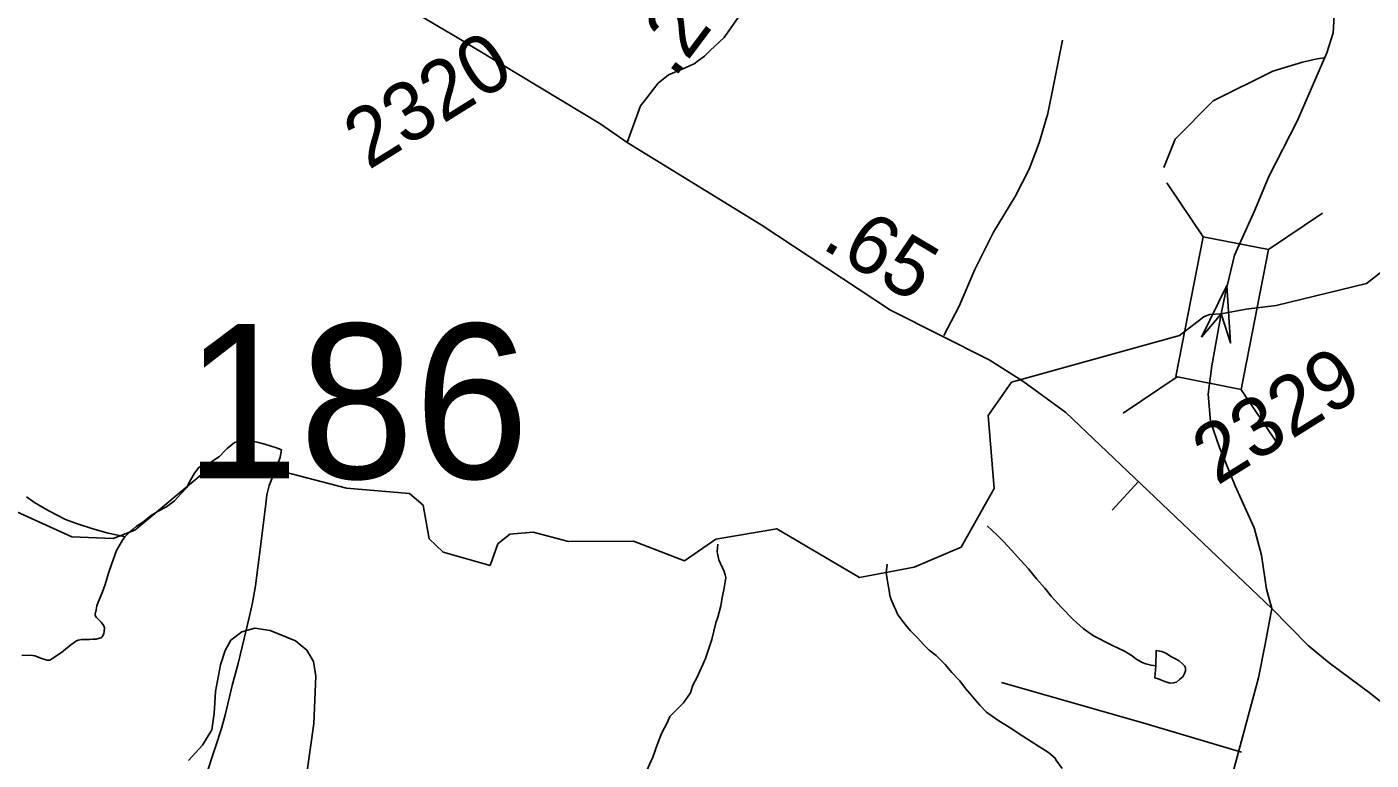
# Model space of a CAD drawing. Extents: x 2001466 to 31450019, y -30647475 to 847247.
# Drawn here: x 2180389 to 2186094, y 761240 to 764352 of the extents above; entities that cross this region are included whole.
import ezdxf

# ---------------------------------------------------------------- set-up
doc = ezdxf.new("R2010")
doc.units = 0
for name, color, linetype in [('Exist Hydrographic Creek Single Shore', 7, 'Continuous'), ('Exist Hydrographic Misc Water Feature', 7, 'Continuous'), ('Exist Road Non-System Type 51', 7, 'Continuous'), ('Exist Road Secondary Mileage Hundredths English Label', 7, 'Continuous'), ('Exist Road Secondary Structure Standard Bridge Attributed CELL', 7, 'Continuous'), ('Exist Road Secondary Structure Standard Bridge CELL', 7, 'Continuous'), ('Exist Road Secondary Structure Standard Bridge Number Label', 7, 'Continuous'), ('Exist Road Secondary Type 51 Attributed', 7, 'Continuous'), ('Exist Road Secondary Type 51 Number Label', 7, 'Continuous')]:
    doc.layers.add(name, color=color, linetype=linetype)

msp = doc.modelspace()

# ---------------------------------------------------------------- linework, layer by layer
at = {"layer": 'Exist Hydrographic Creek Single Shore'}
for points in [[(2185280, 763041.8), (2185383.3, 763121), (2185407.5, 763131.3), (2185458.1, 763134.6), (2185563.6, 763153.3), (2185690.4, 763169.4), (2186074, 763262.7), (2186439, 763547.1), (2186887, 763744.6), (2187202, 764030.1), (2187409.1, 764147.2)], [(2185280, 763041.8), (2184567.1, 762844.2), (2184468, 762701.9), (2184494.1, 762393), (2184354, 762143.3), (2184155.1, 762058.8), (2183922, 762014.4), (2183571.1, 762221.7), (2183313, 762177.8), (2183180.1, 762085.4), (2182962.9, 762168.6), (2182688, 762167.6), (2182538.1, 762206.8), (2182438, 762199), (2182388, 762157.4), (2182355, 762066.2), (2182155, 762122.8), (2182096, 762179.8), (2182070.2, 762321.4), (2182012.1, 762371.8), (2181745.1, 762393.7), (2181311, 762507.5), (2181145.2, 762465), (2180847, 762215.3), (2180755.2, 762181.1), (2180580, 762188), (2180346.1, 762294.4)]]:
    msp.add_lwpolyline(points, dxfattribs=at)
at = {"layer": 'Exist Hydrographic Misc Water Feature'}
for points in [[(2180804.6, 762188), (2180810.1, 762194), (2180822.4, 762206.3), (2180840.5, 762220.3), (2180854, 762232.4), (2180865.9, 762240.4), (2180886, 762254.3), (2180916.1, 762278.6), (2180945.9, 762296.8), (2180981.5, 762315), (2181015.6, 762341), (2181043.3, 762371.3), (2181067, 762397.3), (2181080.8, 762423.7), (2181089.2, 762437.4), (2181100.9, 762457.6), (2181118.5, 762481.7), (2181134.3, 762489.8), (2181158.3, 762495.9), (2181178.6, 762510.3), (2181206.3, 762528.1), (2181228.4, 762552.3), (2181238.3, 762562.6), (2181270.2, 762588.5), (2181306.1, 762596.9), (2181326, 762594.7), (2181344.1, 762593.2), (2181366, 762589.1), (2181398.2, 762581.4), (2181452.1, 762563.5), (2181470, 762557.5)], [(2181154, 761188.3), (2181177.4, 761262.7), (2181191.3, 761300.7), (2181212.8, 761370.5), (2181230.5, 761430.7), (2181260, 761556.9), (2181285.4, 761650.8), (2181310.6, 761756.9), (2181332.2, 761845.3), (2181345.9, 761907.4), (2181359.2, 761979.2), (2181370.7, 762069.5), (2181380.6, 762145.5), (2181390, 762225.2), (2181401.5, 762315.6), (2181407.2, 762365.4), (2181416.9, 762405.3), (2181436.7, 762455.5), (2181454.4, 762497.8), (2181464.2, 762525.5), (2181470, 762557.5)], [(2180387.3, 762357.7), (2180421.7, 762333.9), (2180465.8, 762306.1), (2180514, 762280.6), (2180552.2, 762260.6), (2180600.1, 762244.8), (2180668.6, 762221.5), (2180734.4, 762203.8), (2180794.1, 762189.9)], [(2185179.8, 761640.7), (2185160.1, 761642.8), (2185137.7, 761648.6), (2185121.7, 761654.7), (2185095.9, 761670.4), (2185079.5, 761682.2), (2185047.7, 761702.1), (2184993.6, 761727.6), (2184915.2, 761767.5), (2184871.4, 761799.2), (2184829.1, 761836.9), (2184778.7, 761888.7), (2184736.4, 761936.5), (2184708.6, 761969.9), (2184673.9, 762010), (2184639.7, 762051.7), (2184607.3, 762087.4), (2184567.5, 762131.2), (2184533, 762167.2), (2184507.2, 762195), (2184465, 762234.7)], [(2180367.4, 761683.7), (2180405.1, 761686.1), (2180423.2, 761682.1), (2180447.6, 761672.4), (2180473.8, 761664.3), (2180485.7, 761664.6), (2180501.3, 761674.4), (2180507.2, 761678.8), (2180535.3, 761696.8), (2180553.4, 761710.7), (2180575.1, 761729), (2180589.1, 761739), (2180596.9, 761745.1), (2180606.9, 761749.3), (2180620.8, 761751.3), (2180631.1, 761751.3), (2180654.9, 761751.4), (2180668.8, 761753.3), (2180682.8, 761753.6), (2180696.7, 761757.6), (2180704.7, 761759.7), (2180710.7, 761767.7), (2180715, 761777.6), (2180716.6, 761785.8), (2180718.4, 761801.8), (2180714.8, 761809.7), (2180708.6, 761819.5), (2180704.7, 761825.8), (2180690.4, 761839.7), (2180684.6, 761845.5), (2180680.5, 761851.4), (2180678.1, 761855.4), (2180678.5, 761859.4), (2180682.2, 761877.5), (2180686.1, 761895.5), (2180691.8, 761909.7), (2180699.8, 761929.6), (2180709.8, 761953.6), (2180721.5, 761985.5), (2180735.5, 762033.7), (2180749, 762073.9), (2180768.9, 762130), (2180794.5, 762174.1), (2180804.6, 762188)], [(2180794.1, 762189.9), (2180804.6, 762188)], [(2183011.3, 761177), (2183044.8, 761253), (2183064.4, 761305.2), (2183082.3, 761353.3), (2183108.1, 761401.3), (2183117.8, 761425.4), (2183145.7, 761453.6), (2183175.4, 761483.6), (2183205.3, 761525.7), (2183215, 761558), (2183233, 761592.1), (2183268.5, 761672), (2183295.7, 761752.2), (2183313.4, 761822.2), (2183321.6, 761846.5), (2183333.5, 761894.5), (2183339, 761930.2), (2183346.8, 761962.3), (2183352.5, 761996.4), (2183354.8, 762014.7), (2183352.5, 762026.4), (2183348.4, 762040.4), (2183340.4, 762056.2), (2183332.5, 762074.4), (2183326.1, 762090.4), (2183322.2, 762104.4), (2183320.4, 762116.4), (2183318.1, 762126.1), (2183321.8, 762156.3)], [(2184782.6, 761205), (2184756.1, 761240.6), (2184752.4, 761248.5), (2184724.6, 761272.6), (2184686, 761296.3), (2184615.9, 761341.8), (2184561.3, 761377.6), (2184509.2, 761409.3), (2184461.5, 761443), (2184432.8, 761472.9), (2184412.9, 761496.5), (2184392.8, 761520.7), (2184372.9, 761544.4), (2184348.5, 761576.1), (2184314.4, 761612), (2184286.6, 761645.9), (2184248.2, 761683.7), (2184218.1, 761707.3), (2184194.1, 761731.2), (2184169.5, 761757.3), (2184139.5, 761789), (2184123.3, 761806.8), (2184107.5, 761826.7), (2184085, 761856.9), (2184074.9, 761880.7), (2184069.2, 761892.5), (2184056.7, 761922.4), (2184051, 761938.3), (2184048.7, 761960.5), (2184044.6, 761982.2), (2184040.5, 762008.4), (2184036.2, 762036.2), (2184040.1, 762072.2)], [(2185179.8, 761640.7), (2185181.6, 761704.9), (2185205.6, 761700.9), (2185219.3, 761695.1), (2185233.9, 761687.3), (2185243.5, 761679.3), (2185264, 761669.3), (2185279.6, 761661.3), (2185293.8, 761649.4), (2185302, 761639.7), (2185306.3, 761631.7), (2185305.9, 761619.6), (2185302.2, 761607.6), (2185294.2, 761593.4), (2185282.5, 761583.4), (2185268.6, 761571.3), (2185254.2, 761567.4), (2185240.3, 761567.1), (2185218.3, 761573.2), (2185204.4, 761579), (2185190, 761585.2), (2185176.3, 761588.9), (2185179.8, 761640.7)]]:
    msp.add_lwpolyline(points, dxfattribs=at)
at = {"layer": 'Exist Road Non-System Type 51'}
for points in [[(2184280.6, 763042.7), (2184346, 763167), (2184411.9, 763322), (2184491, 763480.3), (2184583.3, 763632), (2184642.6, 763747.4), (2184685.5, 763859.5), (2184721.7, 763984.8), (2184748.1, 764116.7), (2184784.3, 764294.8)], [(2185896.4, 764220.4), (2185864.5, 764215.7), (2185802.3, 764202.1), (2185676.6, 764164.2), (2185423.7, 764038.4), (2185262.8, 763874.7), (2185214.1, 763755.6)], [(2184994.2, 762301.4), (2185106.8, 762422.2)], [(2181563.7, 761094), (2181607.1, 761395.9), (2181614.9, 761597), (2181605.1, 761658.1), (2181577.5, 761707.3), (2181528.3, 761746.8), (2181421.9, 761790.1), (2181356.9, 761800), (2181301.8, 761784.2), (2181254.5, 761748.7), (2181230.9, 761705.4), (2181211.2, 761644.3), (2181189.5, 761531.9), (2181183.6, 761437.3), (2181173.4, 761368.3), (2181134, 761303.3), (2181074.9, 761238.3)], [(2184525.6, 761569.4), (2185125.4, 761398), (2185543.5, 761274)]]:
    msp.add_lwpolyline(points, dxfattribs=at)
at = {"layer": 'Exist Road Secondary Structure Standard Bridge Attributed CELL'}
msp.add_lwpolyline([(2185373.8, 763035.7), (2185482.2, 763254.1), (2185497.5, 763010.8), (2185458.1, 763134.6)], close=True, dxfattribs=at)
at = {"layer": 'Exist Road Secondary Structure Standard Bridge CELL'}
for p, q in [((2185227.5, 763690.1), (2185381.5, 763461.1)), ((2185887.6, 763560.7), (2185658.5, 763406.8)), ((2185270.1, 762867), (2185041.1, 762713)), ((2185540.9, 762813.9), (2185694.9, 762584.8))]:
    msp.add_line(p, q, dxfattribs=at)
msp.add_lwpolyline([(2185658.5, 763406.8), (2185542.2, 762813.6), (2185265.2, 762867.9), (2185381.5, 763461.1)], close=True, dxfattribs=at)
at = {"layer": 'Exist Road Secondary Type 51 Attributed'}
for points in [[(2179690.4, 765365.9), (2180040.8, 765295.9), (2180213.4, 765261.3), (2180622.1, 765153.5), (2180858.5, 765074.9), (2181089.3, 764970.2), (2181318.4, 764839.3), (2181497.4, 764729.4), (2182207.3, 764311.6), (2182824.2, 763938.8), (2182937.2, 763861.3)], [(2185458.1, 763134.6), (2185475.7, 763223.4), (2185514.6, 763383.6), (2185599.8, 763574.1), (2185659.5, 763716.5), (2185780.3, 763952.1), (2185905.4, 764241.2), (2185932.6, 764326), (2185937.8, 764424.4), (2185928.4, 764507.1), (2185862, 764650.6), (2185787.9, 764814.2), (2185702.9, 764971.2)], [(2182937.2, 763861.3), (2182992.5, 764016.1), (2183015.3, 764044.9), (2183033.5, 764069.2), (2183048.7, 764087.4), (2183068.4, 764113.3), (2183112.4, 764148.2), (2183173.2, 764174), (2183220.2, 764195.3), (2183239.9, 764208.9), (2183264.2, 764227.2), (2183288.9, 764251.5), (2183347.7, 764306.1), (2183397.8, 764377.5), (2183414.5, 764401.8), (2183429.7, 764421.5), (2183454, 764454.9), (2183522.3, 764585.5), (2183551.1, 764649.3)], [(2182937.2, 763861.3), (2183504.9, 763511.6), (2184054.7, 763149.3), (2184473.3, 762938.8), (2184615.1, 762847.7), (2184798.2, 762715.8), (2185672.5, 761883.2)], [(2185672.5, 761883.2), (2185650.1, 761965.7), (2185628.1, 762110.3), (2185597.7, 762225.4), (2185516.7, 762404.5), (2185450.7, 762566.8), (2185411.9, 762676.5), (2185401.7, 762793.6), (2185417.8, 762913.9), (2185458.1, 763134.6)], [(2185346.1, 759130.3), (2185337.7, 759348.1), (2185327.2, 759589), (2185309.4, 759796.3), (2185322, 760095.8), (2185365.9, 760382.7), (2185417.7, 760688.4), (2185500.9, 761164.9), (2185548, 761337.7), (2185615.5, 761589), (2185643.8, 761732.4), (2185672.5, 761883.2)], [(2185672.5, 761883.2), (2185826.3, 761726.2), (2185915.2, 761652.9), (2186091, 761523.1), (2186502.7, 761193.2), (2186702.6, 761025.7), (2187073.6, 760738.8), (2187270.3, 760586.9), (2187713.4, 760218.4), (2187821.2, 760147.2), (2187916.4, 760097.9), (2187978.2, 760081.2), (2188082.8, 760084.3), (2188490.4, 760137.7), (2188811.6, 760175.4), (2189025.6, 760184.9), (2189206.6, 760194.3), (2189306, 760217.3), (2189486, 760280.1), (2189687.9, 760377.7)]]:
    msp.add_lwpolyline(points, dxfattribs=at)

# ---------------------------------------------------------------- texts
at = {"layer": 'Exist Road Secondary Mileage Hundredths English Label'}
for s, rotation, p in [('.20', 53.137, (2183135.8, 764129.4)), ('.65', 329.1569, (2183754.8, 763416.1))]:
    msp.add_text(s, height=250, rotation=rotation, dxfattribs=at).set_placement(p)
at = {"layer": 'Exist Road Secondary Structure Standard Bridge Number Label'}
msp.add_text('186', height=656.17, dxfattribs=at).set_placement((2181056.8, 762435.3))
at = {"layer": 'Exist Road Secondary Type 51 Number Label'}
for s, p in [('2320', (2181838.6, 763742.1)), ('2329', (2185440, 762403.1))]:
    msp.add_text(s, height=250, rotation=31.918, dxfattribs=at).set_placement(p)

doc.saveas('drawing.dxf')
